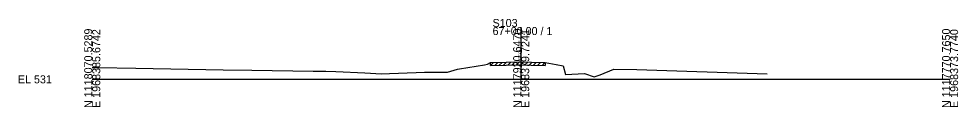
# Model space of a CAD drawing. Extents: x 974 to 1303, y 990 to 14518.
# Drawn here: x 974.3 to 1302.8, y 9990.3 to 10021.1 of the extents above; entities that cross this region are included whole.
import ezdxf

# ---------------------------------------------------------------- set-up
doc = ezdxf.new("R2010")
doc.units = 0
for name, color, linetype in [('Level 10', 7, 'Continuous'), ('Level 60', 7, 'Continuous'), ('Level 61', 7, 'Continuous'), ('Level 63', 7, 'Continuous')]:
    doc.layers.add(name, color=color, linetype=linetype)

msp = doc.modelspace()

# ---------------------------------------------------------------- linework, layer by layer
at = {"layer": 'Level 60'}
for p, q in [((1000, 10004.18), (1002.02, 10004.16)), ((1002.02, 10004.16), (1015.25, 10003.91)), ((1015.25, 10003.91), (1045.73, 10003.33)), ((1128.39, 10003.68), (1137.18, 10005.01)), ((1137.18, 10005.01), (1138.24, 10005.34)), ((1138.24, 10005.34), (1139.33, 10005.82)), ((1139.33, 10005.82), (1144.75, 10005.95)), ((1144.75, 10005.95), (1149.38, 10006.08)), ((1149.38, 10006.08), (1150, 10006.06)), ((1150, 10006.06), (1153.51, 10005.95)), ((1153.51, 10005.95), (1158.41, 10005.82)), ((1158.41, 10005.82), (1162.2, 10005.17)), ((1162.2, 10005.17), (1164.67, 10004.73)), ((1164.67, 10004.73), (1165.48, 10001.64)), ((1045.73, 10003.33), (1055.83, 10003.15)), ((1055.83, 10003.15), (1077.25, 10002.87)), ((1077.25, 10002.87), (1081.63, 10002.84)), ((1081.63, 10002.84), (1085.17, 10002.77)), ((1085.17, 10002.77), (1095.37, 10002.21)), ((1095.37, 10002.21), (1101.19, 10001.89)), ((1101.19, 10001.89), (1104, 10002.02)), ((1104, 10002.02), (1113.31, 10002.41)), ((1113.31, 10002.41), (1116.14, 10002.45)), ((1116.14, 10002.45), (1122.82, 10002.55)), ((1122.82, 10002.55), (1124.18, 10002.53)), ((1124.18, 10002.53), (1127.73, 10003.52)), ((1127.73, 10003.52), (1128.39, 10003.68)), ((1165.48, 10001.64), (1172.1, 10002.05)), ((1172.1, 10002.05), (1175.47, 10000.83)), ((1175.47, 10000.83), (1177.57, 10001.57)), ((1177.57, 10001.57), (1182.46, 10003.59)), ((1182.46, 10003.59), (1190.47, 10003.45)), ((1190.47, 10003.45), (1236.08, 10001.89))]:
    msp.add_line(p, q, dxfattribs=at)
at = {"layer": 'Level 61'}
for p, q in [((1139.33, 10004.82), (1140.36, 10005.84)), ((1139.33, 10004.82), (1139.33, 10005.82)), ((1139.33, 10004.82), (1144.75, 10004.95)), ((1140.83, 10004.85), (1141.86, 10005.88)), ((1142.33, 10004.89), (1143.36, 10005.92)), ((1143.83, 10004.93), (1144.86, 10005.96)), ((1144.75, 10004.95), (1149.38, 10005.08)), ((1145.33, 10004.97), (1146.36, 10006)), ((1146.83, 10005.01), (1147.86, 10006.04)), ((1148.33, 10005.05), (1149.36, 10006.08)), ((1149.38, 10005.08), (1150, 10005.06)), ((1149.83, 10005.06), (1150.8, 10006.04)), ((1150, 10005.06), (1153.51, 10004.95)), ((1151.33, 10005.02), (1152.3, 10005.99)), ((1152.83, 10004.97), (1153.8, 10005.95)), ((1153.51, 10004.95), (1158.41, 10004.82)), ((1154.33, 10004.93), (1155.3, 10005.9)), ((1155.83, 10004.89), (1156.8, 10005.86)), ((1157.33, 10004.85), (1158.3, 10005.82)), ((1158.41, 10005.82), (1158.41, 10004.82)), ((1158.41, 10004.82), (1158.41, 10004.82))]:
    msp.add_line(p, q, dxfattribs=at)
at = {"layer": 'Level 63'}
for p, q in [((1150, 10000), (1150, 10018.23)), ((1000, 10000), (1150, 10000)), ((1150, 10000), (1300, 10000))]:
    msp.add_line(p, q, dxfattribs=at)

# ---------------------------------------------------------------- texts
at = {"layer": 'Level 10'}
msp.add_text('537.06', height=0.9, rotation=90, dxfattribs=at).set_placement((1149.95, 10006.56))
at = {"layer": 'Level 63'}
for s, p in [('S103', (1140, 10018.23)), ('67+00.00 / 1', (1140, 10015.43)), ('EL 531', (974, 9998.6))]:
    msp.add_text(s, height=2.8, dxfattribs=at).set_placement(p)
for s, p in [('N 1118070.5289', (1000, 9990)), ('E 1968385.6742', (1002.8, 9990)), ('N 1117920.6470', (1150, 9990)), ('E 1968379.7241', (1152.8, 9990)), ('N 1117770.7650', (1300, 9990)), ('E 1968373.7740', (1302.8, 9990))]:
    msp.add_text(s, height=2.8, rotation=90, dxfattribs=at).set_placement(p)

doc.saveas('drawing.dxf')
